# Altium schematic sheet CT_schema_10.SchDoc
size 274 x 160 mm
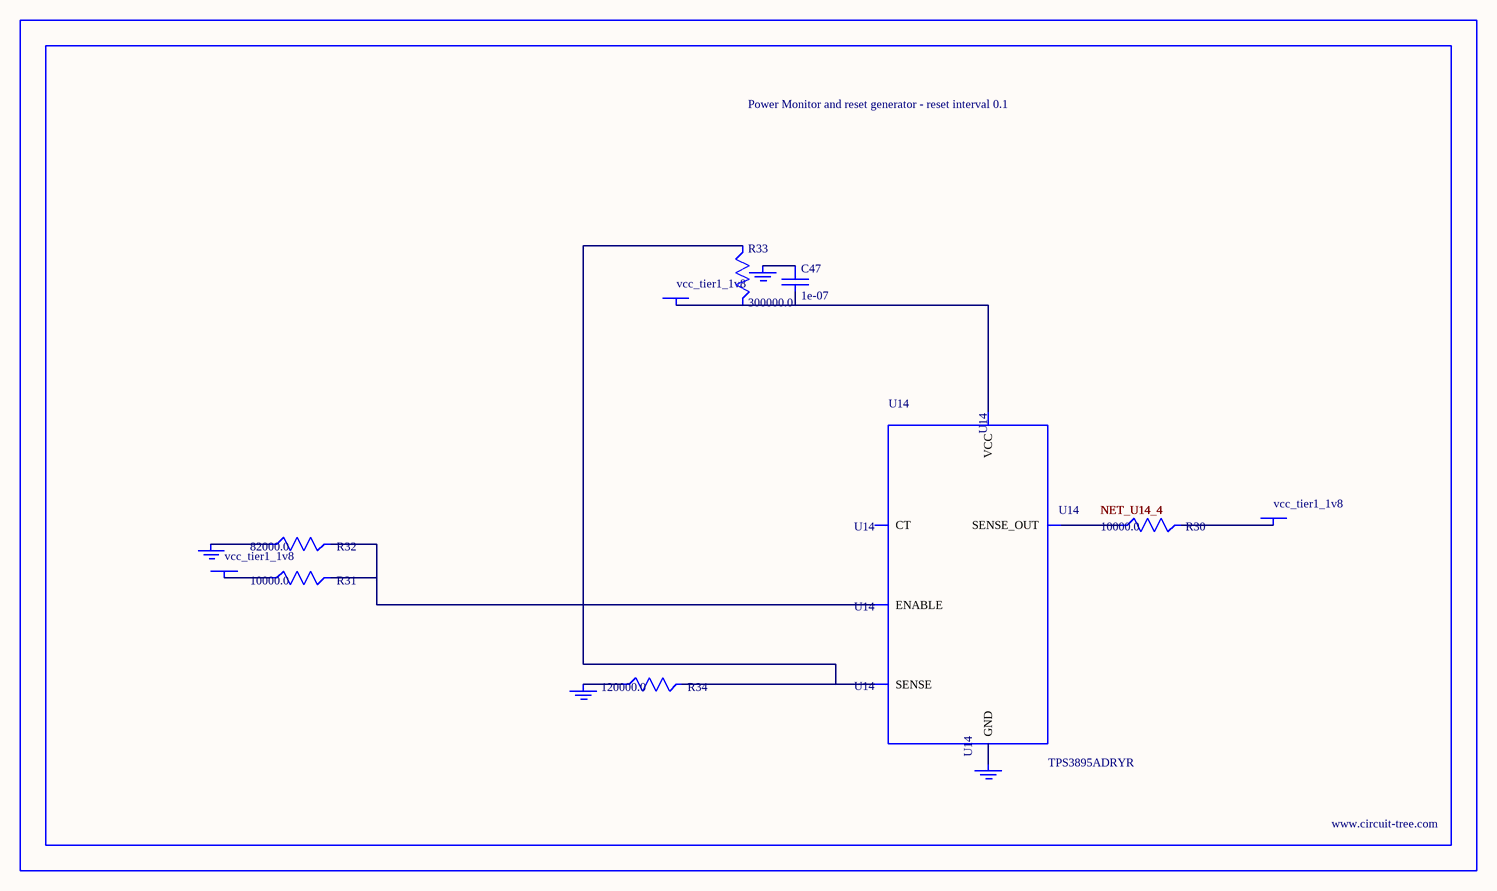
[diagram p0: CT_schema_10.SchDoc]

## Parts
BORDER9  (no value)
C47  1e-07  [C0402]
GND_INSTANCE_9_0  (no value)
GND_INSTANCE_9_1  (no value)
GND_INSTANCE_9_2  (no value)
GND_INSTANCE_9_3  (no value)
POWER_INSTANCE_9_0  vcc_tier1_1v8
POWER_INSTANCE_9_1  vcc_tier1_1v8
POWER_INSTANCE_9_2  vcc_tier1_1v8
R30  10000.0  [R0603]
R31  10000.0  [R0603]
R32  82000.0  [R0603]
R33  300000.0  [R0603]
R34  120000.0  [R0603]
U14  TPS3895ADRYR  [SON-6]

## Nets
NetC47_1: C47.1 GND_INSTANCE_9_2.0(GND)
NetC47_2: C47.2 POWER_INSTANCE_9_2.0(PWR) R33.2 U14.6(VCC)
NetGND_INSTANCE_9_0_0: GND_INSTANCE_9_0.0(GND) R32.1
NetGND_INSTANCE_9_1_0: GND_INSTANCE_9_1.0(GND) R34.1
NetGND_INSTANCE_9_3_0: GND_INSTANCE_9_3.0(GND) U14.2(GND)
NetPOWER_INSTANCE_9_0_0: POWER_INSTANCE_9_0.0(PWR) R31.1
NetPOWER_INSTANCE_9_1_0: POWER_INSTANCE_9_1.0(PWR) R30.2
NetR30_1: R30.1 U14.4(SENSE_OUT)
NetR31_2: R31.2 R32.2 U14.1(ENABLE)
NetR33_1: R33.1 R34.2 U14.3(SENSE)

Not connected (* = marked no-connect by the designer): U14 5(CT)

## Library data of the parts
BORDER9 = BORDER_PAGE9
C47 = C0402C104K3RACTU
GND_INSTANCE_9_0-GND_INSTANCE_9_3 = GND
POWER_INSTANCE_9_0-POWER_INSTANCE_9_2 = PWR
R30 R31 = RC0603JR-0710KL
R32 = RC0603JR-0782KL
R33 = RC0603JR-07300KL
R34 = RC0603JR-07120KL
